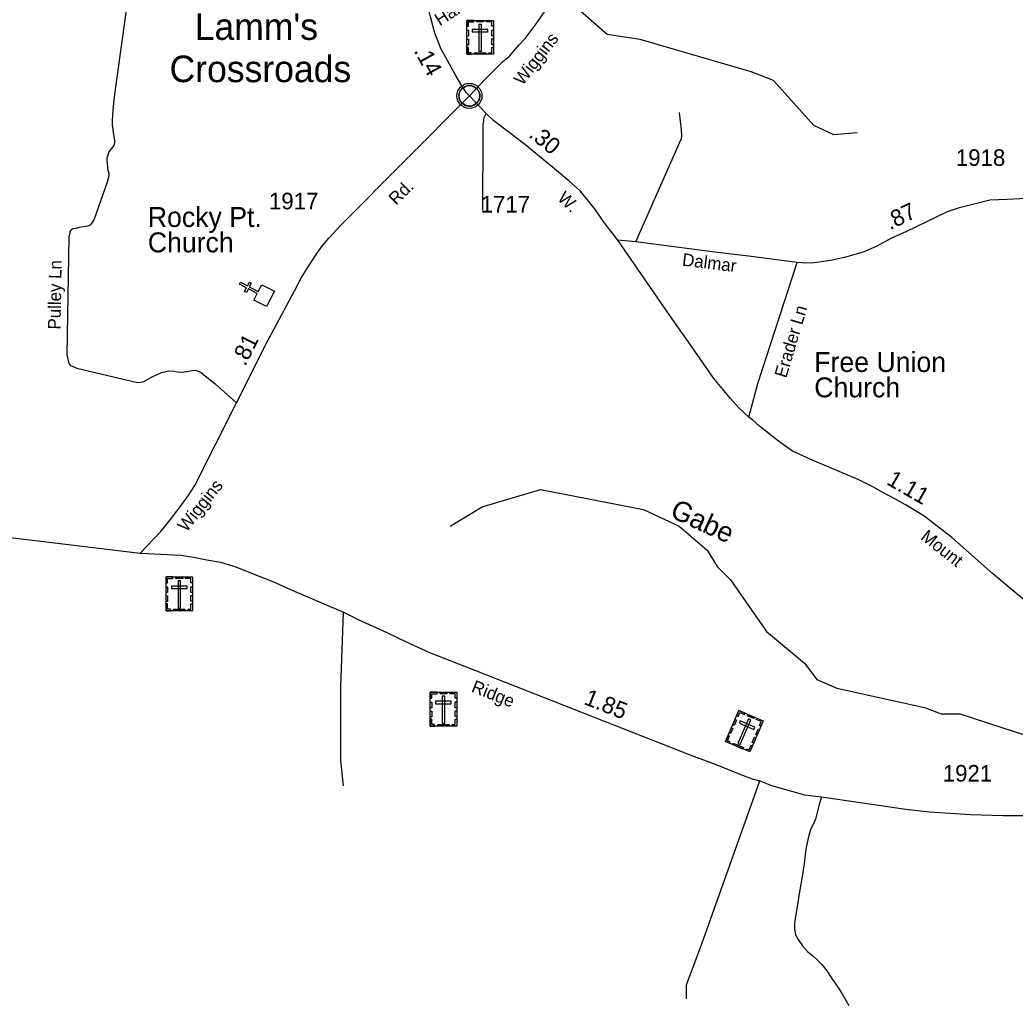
# Model space of a CAD drawing. Extents: x 2220236 to 2384410, y 720751 to 894131.
# Drawn here: x 2273033 to 2280524, y 780491 to 787885 of the extents above; entities that cross this region are included whole.
import ezdxf

# ---------------------------------------------------------------- set-up
doc = ezdxf.new("R2010")
doc.units = 0
for name, color, linetype in [('Exist Civil Demographics Community CELL', 7, 'Continuous'), ('Exist Civil Demographics Community Label', 7, 'Continuous'), ('Exist Cultural Cemetery CELL', 7, 'Continuous'), ('Exist Cultural Church CELL', 7, 'Continuous'), ('Exist Cultural Church Label', 7, 'Continuous'), ('Exist Cultural Church with Cemetery Label', 7, 'Continuous'), ('Exist Hydrographic Creek Single Shore', 7, 'Continuous'), ('Exist Hydrographic Creek Single Shore Label', 7, 'Continuous'), ('Exist Road Non-System Type 51', 7, 'Continuous'), ('Exist Road Non-System Type 51 Label', 7, 'Continuous'), ('Exist Road Secondary Mileage Hundredths English Label', 7, 'Continuous'), ('Exist Road Secondary Type 51 Attributed', 7, 'Continuous'), ('Exist Road Secondary Type 51 Label', 7, 'Continuous'), ('Exist Road Secondary Type 51 Number Label', 7, 'Continuous')]:
    doc.layers.add(name, color=color, linetype=linetype)

msp = doc.modelspace()

# ---------------------------------------------------------------- linework, layer by layer
at = {"layer": 'Exist Civil Demographics Community CELL'}
msp.add_lwpolyline([(2276338.8, 787325.4), (2276339.8, 787331), (2276341.5, 787337.6), (2276344.5, 787344.8), (2276347.4, 787350.5), (2276350.7, 787356.3), (2276354.5, 787361.4), (2276358.4, 787365.8), (2276363, 787370.3), (2276368.6, 787374.9), (2276374, 787378.6), (2276378.9, 787381.5), (2276383.9, 787383.9), (2276389.4, 787386.2), (2276395, 787388), (2276399.3, 787389.2), (2276404.2, 787389.9), (2276408.3, 787390.6), (2276414.7, 787390.9), (2276419.1, 787390.8), (2276424.8, 787390.5), (2276429.7, 787389.8), (2276434.6, 787388.8), (2276439.6, 787387.4), (2276444.8, 787385.5), (2276451.4, 787382.6), (2276457.7, 787379.1), (2276462.7, 787375.5), (2276467.9, 787371.5), (2276471.2, 787368.4), (2276475.3, 787364), (2276479.2, 787359.3), (2276482.3, 787354.7), (2276485.4, 787349.7), (2276487.9, 787344.5), (2276489.9, 787339.5), (2276491.5, 787334.5), (2276492.7, 787329.9), (2276493.8, 787323.9), (2276494.5, 787319.2), (2276494.7, 787313.2), (2276494.5, 787307.4), (2276494, 787301.7), (2276493, 787296.2), (2276491.4, 787290), (2276489.5, 787284.2), (2276487.2, 787279.1), (2276484.1, 787273.1), (2276480.8, 787267.8), (2276477.3, 787263.1), (2276473.1, 787258.4), (2276467.8, 787253.4), (2276462.8, 787249.3), (2276457.8, 787245.9), (2276453.5, 787243.3), (2276446.6, 787240.1), (2276439.5, 787237.4), (2276433.5, 787235.9), (2276426.9, 787234.6), (2276422.5, 787234.2), (2276418, 787233.9), (2276412.4, 787233.9), (2276408.2, 787234.3), (2276402.5, 787235.1), (2276396.6, 787236.4), (2276392, 787237.7), (2276386.8, 787239.5), (2276382.3, 787241.5), (2276378.3, 787243.8), (2276371.5, 787247.8), (2276366, 787252.1), (2276361, 787256.6), (2276356.6, 787261.5), (2276353.4, 787265.4), (2276350.4, 787269.6), (2276346.3, 787276.7), (2276344.6, 787280.2), (2276342.9, 787284.3), (2276340.3, 787292.4), (2276338.8, 787299.5), (2276338.1, 787304.7), (2276337.7, 787311), (2276337.7, 787315.7), (2276338.2, 787322.1)], close=True, dxfattribs=at)
for centre, radius in [((2276416.4, 787313), 94.3), ((2276416.1, 787313.3), 76.7)]:
    msp.add_circle(centre, radius, dxfattribs=at)
at = {"layer": 'Exist Cultural Cemetery CELL'}
for points in [[(2276397.6, 787880.6), (2276596.7, 787880.6), (2276596.7, 787626), (2276397.6, 787626)], [(2276397.6, 787837.3), (2276408.9, 787837.3), (2276408.9, 787869.5), (2276449.5, 787869.5), (2276449.5, 787880.6), (2276397.6, 787880.6)], [(2276471.7, 787880.6), (2276523.5, 787880.6), (2276523.5, 787869.2), (2276471.7, 787869.2)], [(2276506.6, 787851.3), (2276487.9, 787851.3), (2276487.9, 787648.5), (2276506.6, 787648.5)], [(2276596.8, 787837.3), (2276585.4, 787837.3), (2276585.4, 787869.5), (2276544.9, 787869.4), (2276544.9, 787880.6), (2276596.7, 787880.6)], [(2276397.6, 787763.2), (2276397.6, 787806.5), (2276409, 787806.5), (2276409, 787763.2)], [(2276438.4, 787812.6), (2276438.4, 787793.9), (2276556.2, 787793.9), (2276556.2, 787812.6)], [(2276585.3, 787764.2), (2276585.3, 787807.5), (2276596.7, 787807.5), (2276596.7, 787764.2)], [(2276397.6, 787695.9), (2276397.6, 787739.3), (2276409, 787739.3), (2276409, 787695.9)], [(2276585.3, 787698.3), (2276585.3, 787741.6), (2276596.7, 787741.6), (2276596.7, 787698.3)], [(2276430.7, 787626), (2276430.7, 787637.5), (2276408.7, 787637.5), (2276408.7, 787677.9), (2276397.5, 787677.9), (2276397.5, 787626)], [(2276455.1, 787637.5), (2276539.9, 787637.5), (2276539.9, 787626.1), (2276455.1, 787626.1)], [(2276563.6, 787626), (2276563.6, 787637.5), (2276585.6, 787637.5), (2276585.6, 787677.9), (2276596.7, 787677.9), (2276596.7, 787626)], [(2274132.7, 783691.3), (2274331.8, 783691.3), (2274331.8, 783436.6), (2274132.7, 783436.6)], [(2274132.7, 783648), (2274144, 783648), (2274144, 783680.1), (2274184.6, 783680.1), (2274184.6, 783691.3), (2274132.7, 783691.3)], [(2274206.8, 783691.2), (2274258.6, 783691.2), (2274258.6, 783679.8), (2274206.8, 783679.8)], [(2274241.7, 783662), (2274223, 783662), (2274223, 783459.2), (2274241.7, 783459.2)], [(2274331.8, 783647.9), (2274320.5, 783647.9), (2274320.5, 783680.1), (2274279.9, 783680.1), (2274279.9, 783691.2), (2274331.8, 783691.2)], [(2274132.7, 783573.8), (2274132.7, 783617.1), (2274144.1, 783617.1), (2274144.1, 783573.8)], [(2274173.5, 783623.2), (2274173.5, 783604.5), (2274291.2, 783604.5), (2274291.2, 783623.2)], [(2274320.4, 783574.8), (2274320.4, 783618.1), (2274331.8, 783618.1), (2274331.8, 783574.8)], [(2274132.7, 783506.6), (2274132.7, 783549.9), (2274144, 783549.9), (2274144, 783506.6)], [(2274320.4, 783508.9), (2274320.4, 783552.2), (2274331.8, 783552.2), (2274331.8, 783508.9)], [(2274165.8, 783436.7), (2274165.8, 783448.2), (2274143.8, 783448.2), (2274143.8, 783488.6), (2274132.6, 783488.6), (2274132.6, 783436.7)], [(2274190.1, 783448.1), (2274275, 783448.1), (2274275, 783436.7), (2274190.1, 783436.7)], [(2274298.6, 783436.6), (2274298.6, 783448.1), (2274320.6, 783448.1), (2274320.6, 783488.5), (2274331.8, 783488.5), (2274331.8, 783436.6)], [(2276121.5, 782823.3), (2276320.6, 782823.3), (2276320.6, 782568.7), (2276121.5, 782568.7)], [(2276121.5, 782780), (2276132.9, 782780), (2276132.9, 782812.2), (2276173.4, 782812.2), (2276173.4, 782823.3), (2276121.5, 782823.3)], [(2276195.6, 782823.3), (2276247.4, 782823.3), (2276247.4, 782811.9), (2276195.6, 782811.9)], [(2276230.5, 782794), (2276211.9, 782794), (2276211.9, 782591.3), (2276230.5, 782591.3)], [(2276320.7, 782780), (2276309.3, 782780), (2276309.3, 782812.2), (2276268.8, 782812.2), (2276268.8, 782823.3), (2276320.7, 782823.3)], [(2276121.5, 782705.9), (2276121.5, 782749.2), (2276132.9, 782749.2), (2276132.9, 782705.9)], [(2276121.5, 782638.6), (2276121.5, 782682), (2276132.9, 782682), (2276132.9, 782638.6)], [(2276162.3, 782755.3), (2276162.3, 782736.6), (2276280.1, 782736.6), (2276280.1, 782755.3)], [(2276309.2, 782641), (2276309.2, 782684.3), (2276320.6, 782684.3), (2276320.6, 782641)], [(2276309.3, 782706.9), (2276309.3, 782750.2), (2276320.7, 782750.2), (2276320.7, 782706.9)], [(2278444.9, 782686.1), (2278628, 782607.9), (2278528, 782373.7), (2278344.9, 782451.9)], [(2278427.9, 782646.2), (2278438.3, 782641.8), (2278450.9, 782671.4), (2278488.2, 782655.5), (2278492.6, 782665.7), (2278444.9, 782686.1)], [(2276154.6, 782568.8), (2276154.6, 782580.2), (2276132.6, 782580.2), (2276132.6, 782620.7), (2276121.5, 782620.7), (2276121.5, 782568.8)], [(2276287.5, 782568.7), (2276287.5, 782580.2), (2276309.5, 782580.2), (2276309.5, 782620.6), (2276320.6, 782620.6), (2276320.6, 782568.7)], [(2278398.7, 782578.1), (2278415.7, 782617.9), (2278426.2, 782613.4), (2278409.2, 782573.6)], [(2278533.6, 782616.3), (2278516.4, 782623.6), (2278436.8, 782437.2), (2278454, 782429.8)], [(2278455.7, 782607.5), (2278448.3, 782590.3), (2278556.6, 782544), (2278564, 782561.2)], [(2278513, 782657), (2278560.6, 782636.6), (2278556.2, 782626.1), (2278508.5, 782646.5)], [(2278611, 782568), (2278600.6, 782572.4), (2278613.2, 782602), (2278575.9, 782618), (2278580.3, 782628.2), (2278628, 782607.8)], [(2276179, 782580.2), (2276263.8, 782580.2), (2276263.8, 782568.8), (2276179, 782568.8)], [(2278372.3, 782516.2), (2278389.3, 782556.1), (2278399.8, 782551.6), (2278382.8, 782511.8)], [(2278571.8, 782505.3), (2278588.8, 782545.1), (2278599.3, 782540.6), (2278582.3, 782500.8)], [(2278375.3, 782439), (2278379.8, 782449.5), (2278359.6, 782458.2), (2278375.5, 782495.3), (2278365.2, 782499.7), (2278344.8, 782452)], [(2278545.9, 782444.6), (2278562.9, 782484.5), (2278573.4, 782480), (2278556.4, 782440.2)], [(2278402.2, 782439.9), (2278480.3, 782406.6), (2278475.8, 782396.1), (2278397.7, 782429.4)], [(2278497.5, 782386.7), (2278502, 782397.3), (2278522.2, 782388.7), (2278538.1, 782425.8), (2278548.3, 782421.4), (2278528, 782373.7)]]:
    msp.add_lwpolyline(points, close=True, dxfattribs=at)
at = {"layer": 'Exist Cultural Church CELL'}
msp.add_lwpolyline([(2274793.6, 785775.4), (2274819.9, 785825.9), (2274752.4, 785861.1), (2274737.6, 785832.8), (2274723.4, 785840.2), (2274738.2, 785868.5), (2274684.9, 785896.3), (2274692.3, 785910.5), (2274745.6, 785882.7), (2274760.4, 785911.1), (2274774.6, 785903.7), (2274759.8, 785875.3), (2274827.3, 785840.1), (2274854, 785891.2), (2274948.4, 785842), (2274888, 785726.2)], close=True, dxfattribs=at)
at = {"layer": 'Exist Hydrographic Creek Single Shore'}
for points in [[(2279334, 787034.9), (2279159.1, 787018.8), (2279009, 787090.9), (2278706.1, 787428.3), (2278538, 787494.1), (2277703, 787737.6), (2277453, 787775.6), (2277252.1, 787950.3), (2277065.9, 788190.3), (2276846.9, 788385.1), (2276611.1, 788760.6), (2276576, 788876.1), (2276573, 789184.4), (2276660.9, 789582.8), (2276658.1, 789891.1), (2276590, 790066.4), (2276597, 790207.3), (2276850, 790818.7), (2277030, 791087.2), (2277244.9, 791246.8)], [(2276271.9, 784074.1), (2276512, 784220), (2276951.9, 784348.7), (2277728, 784198.2), (2277996, 784074.6), (2278206, 783893.1), (2278282.1, 783770.2), (2278383, 783669.8), (2278653, 783280.4), (2278939.1, 783041.7), (2279030.9, 782918.4), (2279182, 782853), (2279841.1, 782708.2), (2279967, 782659.7), (2280108.1, 782660), (2281428, 782232.7)]]:
    msp.add_lwpolyline(points, dxfattribs=at)
at = {"layer": 'Exist Road Non-System Type 51'}
for points in [[(2273835.4, 787977.5), (2273818.6, 787849.5), (2273741.8, 787305.1), (2273732.7, 787206.9), (2273727.5, 787125), (2273727.6, 787095), (2273736.5, 787021), (2273744.8, 786977.1), (2273744.9, 786963.1), (2273739.2, 786939), (2273701.6, 786890.8), (2273693.9, 786866.8), (2273688.1, 786844.7), (2273686.2, 786822.7), (2273695, 786752.8), (2273701.1, 786730.9), (2273701.3, 786712.9), (2273699.5, 786700.9), (2273689.7, 786662.7), (2273592.4, 786384), (2273576.7, 786359.9), (2273560.9, 786339.7), (2273542.9, 786331.5), (2273479.1, 786321), (2273453.2, 786314.7), (2273431.1, 786312.6), (2273421.2, 786306.4), (2273409.3, 786292.2), (2273407.6, 786276.3), (2273401.7, 786252.2), (2273386.1, 785362.6), (2273400.8, 785298.7), (2273414.9, 785282.8), (2273461, 785263.3), (2273917.9, 785155.6), (2273945.9, 785157.9), (2273965.8, 785162.1), (2274027.3, 785198.6), (2274099, 785231.3), (2274154.8, 785243.7), (2274194.9, 785240.1), (2274217, 785234.4), (2274253, 785232.7), (2274302.9, 785239.3), (2274330.7, 785245.5), (2274354.8, 785247.6), (2274380.7, 785237.9), (2274400.9, 785228), (2274503.6, 785145.1), (2274662, 785002.9)], [(2276517, 786452), (2276519.2, 787020), (2276520.3, 787097.3), (2276524, 787119.2), (2276524, 787131.2), (2276527.8, 787149.3), (2276543.8, 787181.1)], [(2277668.1, 786214.4), (2277998.8, 786959.1), (2278012.5, 786993.2), (2278014.3, 787011.2), (2278013.8, 787057.2), (2277996.7, 787187.1)], [(2278519.9, 784894), (2278587.4, 785148.8), (2278882.9, 786057.9)], [(2275469.6, 782119.7), (2275447.7, 782311.3), (2275448.7, 782862.7), (2275469.3, 783425.1)], [(2278051.5, 780515.5), (2278051.5, 780621.3), (2278165.4, 780930.7), (2278602, 782155.8)], [(2279065.7, 782036.4), (2279047.6, 781969.5), (2279035, 781917), (2279020.5, 781868.2), (2279004.3, 781828.4), (2278986.2, 781795.8), (2278975.3, 781763.3), (2278962.7, 781714.4), (2278950, 781642.1), (2278937.4, 781533.5), (2278922.9, 781450.3), (2278901.2, 781321), (2278875.9, 781161.8), (2278863.2, 781089.4), (2278863.2, 781044.2), (2278872.3, 780997.1), (2278890.4, 780962.8), (2278924.7, 780913.9), (2278964.5, 780868.7), (2279002.4, 780839.8), (2279033.2, 780809), (2279069.3, 780774.6), (2279107.3, 780725.8), (2279143.5, 780667.9), (2279185, 780610), (2279223, 780553.9), (2279273.6, 780466.2)]]:
    msp.add_lwpolyline(points, dxfattribs=at)
at = {"layer": 'Exist Road Secondary Type 51 Attributed'}
for points in [[(2276416.4, 787313), (2276543.8, 787447.2), (2276668.9, 787572.4), (2276718.1, 787612.7), (2276787.4, 787695.4), (2276836.5, 787745.7), (2276925.9, 787866.5), (2277111.4, 788139.3)], [(2276416.4, 787313), (2276394, 787335.4), (2276360.5, 787389), (2276315.8, 787460.6), (2276200.2, 787669.6), (2276155.5, 787785.9), (2276123.6, 787909), (2276108, 787969.4)], [(2269908.1, 787520), (2269977.8, 787491.4), (2270027.8, 787462.8), (2270057.7, 787437.6), (2270092, 787409.2), (2270108.4, 787389.7), (2270129.7, 787373.6), (2270213.7, 787286.3), (2270899.2, 786348), (2272213.5, 784525.7), (2272320.6, 784375.6), (2272374.2, 784305.9), (2272434.9, 784234.5), (2272446.1, 784223.2), (2272496.9, 784171.2), (2272567, 784123.7), (2272674.2, 784059.4), (2272742.9, 784037.2), (2272800.5, 784016.9), (2272899.2, 783995.1), (2273939.3, 783870.9)], [(2273939.3, 783870.9), (2274090.4, 784031.8), (2274174.8, 784134.1), (2274253, 784239.2), (2274304.4, 784310.7), (2274349.1, 784380.1), (2274662, 785002.9), (2274889.9, 785452.4), (2275100, 785844.9), (2275153.7, 785945.5), (2275202.8, 786026), (2275263.2, 786119.9), (2275303.4, 786175.8), (2275359.3, 786240.7), (2275446.4, 786338), (2276416.4, 787313)], [(2277533.8, 786226.2), (2277431, 786360.3), (2277366.2, 786454.3), (2277305.9, 786530.3), (2277250, 786597.4), (2277165.1, 786673.4), (2277042.1, 786776.3), (2276832.1, 786948.5), (2276599.6, 787125.3), (2276543.8, 787181.1), (2276494.6, 787230.3), (2276416.4, 787313)], [(2281998.5, 786624), (2280701, 786546.5), (2280464.9, 786532.7), (2280334, 786526.7), (2280207, 786495.9), (2280095.9, 786468.1), (2280012.6, 786440.3), (2279702.4, 786289.5), (2279594.9, 786240.6), (2279483.5, 786181.5), (2279380, 786136.4), (2279248.2, 786099.4), (2279148.6, 786076.4), (2279014.8, 786055.2), (2278946.8, 786054.4), (2278882.9, 786057.9), (2278536.7, 786102.7), (2278264.5, 786136.1), (2277668.1, 786214.4), (2277533.8, 786226.2)], [(2280596.6, 783513), (2280495.4, 783598.9), (2280354.3, 783718.6), (2280176.4, 783875.1), (2280047.5, 783988.7), (2279835.9, 784151.3), (2279699.4, 784234.2), (2279619.6, 784280.2), (2279524.5, 784329.3), (2279457, 784366.2), (2279346.6, 784421.4), (2278987.7, 784574.9), (2278849.6, 784639.3), (2278742.3, 784713), (2278599.6, 784826.5), (2278550.6, 784872.6), (2278523, 784891), (2278443.2, 784967.7), (2278381.8, 785035.2), (2278256.1, 785185.6), (2278050.5, 785480.3), (2277930.9, 785652.1), (2277533.8, 786226.2)], [(2273939.3, 783870.9), (2274243.9, 783855.3), (2274339.9, 783840.1), (2274440.1, 783821), (2274543.5, 783802), (2274657.5, 783768.4), (2274762.6, 783726), (2274834.1, 783696.9), (2274941.4, 783654.4), (2275109, 783578.4), (2275469.3, 783425.1), (2275579.8, 783370), (2275794.7, 783272.2), (2275935, 783205.5), (2276115.9, 783123.2), (2276391.8, 783014.8), (2278082.1, 782350), (2278266.6, 782281.8), (2278453.2, 782207.5), (2278545, 782172.1), (2278602, 782155.8), (2278691.5, 782120.6), (2278938.6, 782050.2), (2279065.7, 782036.4), (2279701.2, 781943.4), (2279879.3, 781923.1), (2280187.4, 781904), (2280435.4, 781896.5), (2280629.1, 781896.2)]]:
    msp.add_lwpolyline(points, dxfattribs=at)

# ---------------------------------------------------------------- texts
at = {"layer": 'Exist Civil Demographics Community Label'}
for s, p in [("Lamm's", (2274348.8, 787734.6)), ('Crossroads', (2274159.4, 787416.2))]:
    msp.add_text(s, height=200, dxfattribs=at).set_placement(p)
at = {"layer": 'Exist Cultural Church Label'}
for s, p in [('Rocky Pt.', (2273995.6, 786326.1)), ('Church', (2273995.6, 786135.1))]:
    msp.add_text(s, height=150, dxfattribs=at).set_placement(p)
at = {"layer": 'Exist Cultural Church with Cemetery Label'}
for s, p in [('Free Union', (2279012.2, 785234.5)), ('Church', (2279012.2, 785043.5))]:
    msp.add_text(s, height=150, dxfattribs=at).set_placement(p)
at = {"layer": 'Exist Hydrographic Creek Single Shore Label'}
msp.add_text('Gabe', height=150, rotation=335.2423, dxfattribs=at).set_placement((2277918.3, 784146.6))
at = {"layer": 'Exist Road Non-System Type 51 Label'}
for s, rotation, p in [('Pulley Ln', 88.98643, (2273338.5, 785553.3)), ('Erader Ln', 73.37383, (2278801.4, 785184))]:
    msp.add_text(s, height=95, rotation=rotation, dxfattribs=at).set_placement(p)
at = {"layer": 'Exist Road Secondary Mileage Hundredths English Label'}
for s, rotation, p in [('.14', 298.95736, (2275995.4, 787652.3)), ('.30', 320.65957, (2276856.2, 787009.5)), ('.87', 25.93063, (2279582.5, 786300.7)), ('.81', 63.10865, (2274728.5, 785272.3)), ('1.11', 330.00573, (2279549.1, 784393.1)), ('1.85', 338.53161, (2277271.4, 782736))]:
    msp.add_text(s, height=125, rotation=rotation, dxfattribs=at).set_placement(p)
at = {"layer": 'Exist Road Secondary Type 51 Label'}
for s, rotation, p in [('Hall Dr.', 32.45856, (2276193.1, 787836.5)), ('Wiggins', 52.20756, (2276816.9, 787385.3)), ('Rd.', 44.69671, (2275864.8, 786485.2)), ('W.', 316.4977, (2277072.6, 786534.7)), ('Dalmar', 353.00473, (2278013.8, 786035.5)), ('Wiggins', 51.52959, (2274286.4, 784024)), ('Mount', 321.81222, (2279806.9, 783979.9)), ('Ridge', 338.24387, (2276424.3, 782829.4))]:
    msp.add_text(s, height=95, rotation=rotation, dxfattribs=at).set_placement(p)
at = {"layer": 'Exist Road Secondary Type 51 Number Label'}
for s, p in [('1918', (2280078.2, 786785.8)), ('1917', (2274907.8, 786458.9)), ('1717', (2276500.9, 786434.7)), ('1921', (2279979.6, 782150.7))]:
    msp.add_text(s, height=125, dxfattribs=at).set_placement(p)

doc.saveas('drawing.dxf')
